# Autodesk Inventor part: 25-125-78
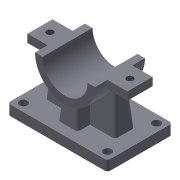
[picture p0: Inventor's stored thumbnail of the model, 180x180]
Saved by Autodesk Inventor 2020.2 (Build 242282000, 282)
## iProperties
Created: 2005-02
Part Number: 25-125-78
Document SubType Name: Modeling
Designer: F.Stasiak
Manufacturer: Standard
Standards Organization: Custom
Description: Podpora główna
Authority: B.S.
Material: St1203
Mass: 1118.62 g
Surface Area: 322.623 cm^2
Volume: 142.499 cm^3
Density: 7.85 g/cm^3
Appearance: Metal-Stal
Manager: www.cadconsulting.pl
Company: Fabian Stasiak CAD Consulting
Author: F.Stasiak
Subject: Zbiór ćwiczeń. Autodesk Inventor 2020. Kurs podstawowy
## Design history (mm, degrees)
sketch "Szkic1"
  geometry: L1 (-50, 32.5)-(50, 32.5); L2 (50, 32.5)-(50, -32.5); L3 (50, -32.5)-(-50, -32.5); L4 (-50, -32.5)-(-50, 32.5); L5 (0, 32.5)-(0, -32.5); 2 further points
  constraints: 10 end point, 3 midpoint, 2 parallel, 1 coincident, 1 horizontal, 1 perpendicular
  dimensions: "d0" = 100 distance of L2.end L3.end; "d106" = 65 distance of L1.end L2.end
extrude "Wyciągnięcie proste1" new body sketch "Szkic1" distance "d2" = 10; taper "d3" = 0 deg
sketch "Szkic2"
  geometry: L1 (50, 32.5)-(50, -32.5); L2 (-50, 32.5)-(50, 32.5) reference; L3 (-50, -32.5)-(-50, 32.5) reference; L4 (50, -32.5)-(-50, -32.5) reference; L5 (-35, 10)-(35, 10); L6 (35, 10)-(35, -10); L7 (35, -10)-(-35, -10); L8 (-35, -10)-(-35, 10); 4 further points
  constraints: 10 end point, 4 midpoint, 4 parallel, 1 horizontal alignment, 1 vertical alignment
  dimensions: "d4" = 20 distance of L5.end L6.end; "d118" = 70 distance of L5.start L5.end
extrude "Wyciągnięcie proste2" join sketch "Szkic2" distance "d5" = 50; taper "d6" = -5 deg
sketch "Szkic3"
  geometry: L1 (30.626, 60)-(-30.626, 60) reference; A1 r 30 centre (0, 60) between (-30, 60) and (30, 60)
  constraints: 2 end point, 2 point on circle, 2 point on line, 1 centre point, 1 midpoint
  dimensions: "d119" = 60 diameter of A1
extrude "Wyciągnięcie proste3" join sketch "Szkic3" stored distance "d7" = 50; taper "d8" = 0 deg
sketch "Szkic4"
  geometry: C1 r 22.5 at (0, 60)
  constraints: 1 centre point
  dimensions: "d9" = 45 diameter of C1
extrude "Wyciągnięcie proste4" cut sketch "Szkic4" extent not by distance; stored distance "d10" = 10; taper "d11" = 0 deg
sketch "Szkic5"
  geometry: L1 (50, -32.5)-(-50, -32.5); L2 (-10, 22.5)-(10, 22.5) reference; L3 (10, 22.5)-(10, -22.5) reference; L4 (10, -22.5)-(-10, -22.5) reference; L5 (-10, -22.5)-(-10, 22.5) reference; L6 (50, 32.5)-(50, -32.5) reference; 2 further points
  constraints: 10 end point, 3 horizontal, 2 midpoint, 2 parallel, 2 vertical, 1 horizontal alignment, 1 perpendicular
extrude "Wyciągnięcie proste5" join sketch "Szkic5" stored distance "d14" = 10; taper "d15" = -5 deg
sketch "Szkic10"
  geometry: L1 (60, 45)-(52, 45) reference; L2 (60, 20)-(60, 45) reference; L3 (52, 20)-(60, 20) reference; L4 (52, 45)-(52, 20) reference
extrude "Wyciągnięcie proste10" join sketch "Szkic10" stored distance "d31" = 10; taper "d32" = 0 deg
hole "Otwór3" diameter "d51" = 8; stored, may be unused: countersink angle "d55" = 90 deg, drill point angle "d57" = 118 deg; dims "d49" = 8, "d50" = 8, "d52" = 6, "d53" = 4, "d54" = 2, "d56" = 8
hole "Otwór4" diameter "d60" = 8; stored, may be unused: countersink angle "d64" = 90 deg, drill point angle "d66" = 118 deg; dims "d58" = 8, "d59" = 8, "d61" = 6, "d62" = 4, "d63" = 2, "d65" = 8
hole "Otwór5" diameter "d69" = 8; stored, may be unused: countersink angle "d73" = 90 deg, drill point angle "d75" = 118 deg; dims "d67" = 8, "d68" = 8, "d70" = 6, "d71" = 4, "d72" = 2, "d74" = 8
hole "Otwór6" diameter "d78" = 8; stored, may be unused: countersink angle "d82" = 90 deg, drill point angle "d84" = 118 deg; dims "d76" = 8, "d77" = 8, "d79" = 6, "d80" = 4, "d81" = 2, "d83" = 8
sketch "Szkic13"
  geometry: L1 (-50, 12.5)-(-50, -12.5) reference; L2 (-50, -12.5)-(-30, -12.5) reference; 4 further points
  constraints: 2 midpoint, 1 horizontal alignment, 1 vertical alignment
hole "Otwór10" sketch "Szkic13" at (-40, 0) diameter "d120" = 6.647; stored, may be unused: countersink angle "d124" = 90 deg, drill point angle "d126" = 118 deg; dims "d121" = 16, "d122" = 4, "d123" = 2, "d125" = 22.2
mirror "Odbicie lustrzane1"
fillet "Zaokrąglenie7" dims "d114" = 3
fillet "Zaokrąglenie8" dims "d116" = 3
node "Bryła1"
node "Korpusy bryłowe"
node "Korpusy powierzchniowe"
